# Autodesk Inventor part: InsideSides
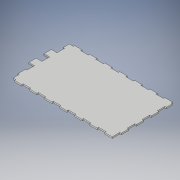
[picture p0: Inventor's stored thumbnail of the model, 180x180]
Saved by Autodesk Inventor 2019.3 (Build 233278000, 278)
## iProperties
Created: 2020-02
Part Number: InsideSides
Material: Generic
Document SubType Name: Modeling
Designer: KrystynWikoff
Density: 1 g/cm^3
Appearance: Default
Author: KrystynWikoff
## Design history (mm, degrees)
sketch "Sketch1"
  geometry: L1 (0, 0)-(174.142, 0); L2 (174.142, 0)-(174.142, -101.6); L3 (174.142, -101.6)-(0, -101.6); L4 (0, -101.6)-(0, 0)
  constraints: 8 end point, 2 parallel, 1 horizontal, 1 perpendicular
  dimensions: "d0" = 101.6 distance of L3.end L1.start; "d1" = 174.1424 distance of L1.start L1.end
extrude "Extrusion1" new body sketch "Sketch1" distance "d2" = 2.3622; taper "d3" = 0 deg
sketch "Sketch2" dims "d13" = 25.4
  geometry: L1 (-15.062, 0)-(-27.762, 0); L2 (-27.762, 0)-(-27.762, 2.362); L3 (-27.762, 2.362)-(-15.062, 2.362); L4 (-15.062, 2.362)-(-15.062, 0); L5 (0, 0)-(0, 101.6) reference; L6 (-174.142, 0)-(0, 0) reference; L7 (-40.462, 0)-(-53.162, 0); L8 (-53.162, 0)-(-53.162, 2.362); L9 (-53.162, 2.362)-(-40.462, 2.362); L10 (-40.462, 2.362)-(-40.462, 0); L11 (-65.862, 0)-(-78.562, 0); L12 (-78.562, 0)-(-78.562, 2.362); L13 (-78.562, 2.362)-(-65.862, 2.362); L14 (-65.862, 2.362)-(-65.862, 0); L15 (-91.262, 0)-(-103.962, 0); L16 (-103.962, 0)-(-103.962, 2.362); L17 (-103.962, 2.362)-(-91.262, 2.362); L18 (-91.262, 2.362)-(-91.262, 0); L19 (-116.662, 0)-(-129.362, 0); L20 (-129.362, 0)-(-129.362, 2.362); L21 (-129.362, 2.362)-(-116.662, 2.362); L22 (-116.662, 2.362)-(-116.662, 0); L23 (-142.062, 0)-(-154.762, 0); L24 (-154.762, 0)-(-154.762, 2.362); L25 (-154.762, 2.362)-(-142.062, 2.362); L26 (-142.062, 2.362)-(-142.062, 0); L27 (-167.462, 0)-(-180.162, 0); L28 (-180.162, 0)-(-180.162, 2.362); L29 (-180.162, 2.362)-(-167.462, 2.362); L30 (-167.462, 2.362)-(-167.462, 0)
  constraints: 56 end point, 2 horizontal, 2 parallel, 1 collinear, 1 perpendicular, 47 other
  dimensions: "d4" = 15.0622 distance between parallel lines of L5 L4; "d5" = 12.7 distance of L2.end L3.end; "d6" = 2.3622 distance of L3.end L1.start; "d7" = 0 distance between parallel lines of L6 L1; "d10" = 25.4 distance of L1.start L7.start
extrude "Extrusion2" cut sketch "Sketch2" distance "d15" = 2.3622; taper "d16" = 0 deg
sketch "Sketch3" dims "d25" = 25.4, "d35" = 25.4, "d44" = 25.4
  geometry: L1 (0, 0)-(0, 101.6) reference; L2 (0, 0)-(-2.362, 0); L3 (-2.362, 0)-(-2.362, 12.7); L4 (-2.362, 12.7)-(0, 12.7); L5 (0, 12.7)-(0, 0); L6 (-15.062, 0)-(0, 0) reference; L7 (0, 25.4)-(-2.362, 25.4); L8 (-2.362, 25.4)-(-2.362, 38.1); L9 (-2.362, 38.1)-(0, 38.1); L10 (0, 38.1)-(0, 25.4); L11 (0, 50.8)-(-2.362, 50.8); L12 (-2.362, 50.8)-(-2.362, 63.5); L13 (-2.362, 63.5)-(0, 63.5); L14 (0, 63.5)-(0, 50.8); L15 (0, 76.2)-(-2.362, 76.2); L16 (-2.362, 76.2)-(-2.362, 88.9); L17 (-2.362, 88.9)-(0, 88.9); L18 (0, 88.9)-(0, 76.2); L19 (-174.142, 101.6)-(-174.142, 2.362) reference; L20 (-174.142, 0)-(-171.78, 0); L21 (-171.78, 0)-(-171.78, 12.7); L22 (-171.78, 12.7)-(-174.142, 12.7); L23 (-174.142, 12.7)-(-174.142, 0); L24 (-167.462, 0)-(-154.762, 0) reference; L25 (-171.78, 38.1)-(-174.142, 38.1); L26 (-171.78, 25.4)-(-171.78, 38.1); L27 (-174.142, 38.1)-(-174.142, 25.4); L28 (-174.142, 25.4)-(-171.78, 25.4); L29 (-171.78, 63.5)-(-174.142, 63.5); L30 (-171.78, 50.8)-(-171.78, 63.5); L31 (-174.142, 63.5)-(-174.142, 50.8); L32 (-174.142, 50.8)-(-171.78, 50.8); L33 (-171.78, 88.9)-(-174.142, 88.9); L34 (-171.78, 76.2)-(-171.78, 88.9); L35 (-174.142, 88.9)-(-174.142, 76.2); L36 (-174.142, 76.2)-(-171.78, 76.2); L37 (-171.78, 114.3)-(-174.142, 114.3); L38 (-171.78, 101.6)-(-171.78, 114.3); L39 (-174.142, 114.3)-(-174.142, 101.6); L40 (-174.142, 101.6)-(-171.78, 101.6); L41 (0, 101.6)-(-2.362, 101.6); L42 (-2.362, 101.6)-(-2.362, 114.3); L43 (-2.362, 114.3)-(0, 114.3); L44 (0, 114.3)-(0, 101.6)
  constraints: 80 end point, 4 parallel, 3 vertical, 2 horizontal, 2 perpendicular, 2 point on line, 64 other
  dimensions: "d17" = 0 distance between parallel lines of L6 L2; "d18" = 12.7 distance of L2.end L3.end; "d19" = 2.3622 distance of L2.start L2.end; "d22" = 25.4 distance of L2.start L7.start; "d27" = 0 distance between parallel lines of L24 L20; "d28" = 2.3622 distance of L20.start L20.end; "d29" = 12.7 distance of L20.end L21.end; "d32" = 25.4 distance of L21.end L25.start; "d41" = 25.4 distance of L15.end L41.end
extrude "Extrusion3" cut sketch "Sketch3" distance "d37" = 2.3622; taper "d38" = 0 deg
sketch "Sketch4" dims "d56" = 25.4
  geometry: L1 (0, 101.6)-(-174.142, 101.6) reference; L2 (-27.762, 101.6)-(-15.062, 101.6); L3 (-15.062, 101.6)-(-15.062, 99.238); L4 (-15.062, 99.238)-(-27.762, 99.238); L5 (-27.762, 99.238)-(-27.762, 101.6); L6 (0, 88.9)-(0, 101.6) reference; L7 (0, 101.6)-(-2.362, 101.6); L8 (-2.362, 101.6)-(-2.362, 99.238); L9 (-2.362, 99.238)-(0, 99.238); L10 (0, 99.238)-(0, 101.6); L11 (-27.762, 101.6)-(-27.762, 99.238); L12 (-53.162, 101.6)-(-40.462, 101.6); L13 (-40.462, 101.6)-(-40.462, 99.238); L14 (-40.462, 99.238)-(-53.162, 99.238); L15 (-53.162, 99.238)-(-53.162, 101.6); L16 (-53.162, 101.6)-(-53.162, 99.238); L17 (-78.562, 101.6)-(-65.862, 101.6); L18 (-65.862, 101.6)-(-65.862, 99.238); L19 (-65.862, 99.238)-(-78.562, 99.238); L20 (-78.562, 99.238)-(-78.562, 101.6); L21 (-78.562, 101.6)-(-78.562, 99.238); L22 (-103.962, 101.6)-(-91.262, 101.6); L23 (-91.262, 101.6)-(-91.262, 99.238); L24 (-91.262, 99.238)-(-103.962, 99.238); L25 (-103.962, 99.238)-(-103.962, 101.6); L26 (-103.962, 101.6)-(-103.962, 99.238); L27 (-129.362, 101.6)-(-116.662, 101.6); L28 (-116.662, 101.6)-(-116.662, 99.238); L29 (-116.662, 99.238)-(-129.362, 99.238); L30 (-129.362, 99.238)-(-129.362, 101.6); L31 (-129.362, 101.6)-(-129.362, 99.238); L32 (-154.762, 101.6)-(-142.062, 101.6); L33 (-142.062, 101.6)-(-142.062, 99.238); L34 (-142.062, 99.238)-(-154.762, 99.238); L35 (-154.762, 99.238)-(-154.762, 101.6); L36 (-154.762, 101.6)-(-154.762, 99.238); L37 (-180.162, 101.6)-(-167.462, 101.6); L38 (-167.462, 101.6)-(-167.462, 99.238); L39 (-167.462, 99.238)-(-180.162, 99.238); L40 (-180.162, 99.238)-(-180.162, 101.6); 1 further point
  constraints: 76 end point, 4 parallel, 3 horizontal, 2 perpendicular, 1 point on line, 66 other
  dimensions: "d46" = 15.0622 distance between parallel lines of L6 L3; "d47" = 12.7 distance of L3.end L4.end; "d48" = 2.3622 distance of L4.end L2.start; "d49" = 2.3622 distance of L8.end L9.end; "d50" = 2.3622 distance of L7.end L8.end; "d53" = 25.4 distance of L7.end L11.start
extrude "Extrusion4" cut sketch "Sketch4" extent not by distance; stored distance "d58" = 0; taper "d59" = 0 deg
sketch "Sketch5"
  geometry: L1 (25.4, 0)-(12.7, 0) reference; L2 (0, 2.362)-(12.7, 2.362) reference; L3 (12.7, 0)-(0, 0); L4 (0, 0)-(0, 2.362); L5 (0, 2.362)-(12.7, 2.362); L6 (12.7, 2.362)-(12.7, 0); L7 (-12.7, 0)-(-25.4, 0) reference; L8 (-25.4, 2.362)-(-12.7, 2.362) reference; L9 (-12.7, 0)-(-25.4, 0); L10 (-25.4, 0)-(-25.4, 2.362); L11 (-25.4, 2.362)-(-12.7, 2.362); L12 (-12.7, 2.362)-(-12.7, 0); 1 further point
  constraints: 16 end point, 4 parallel, 2 horizontal, 2 perpendicular
extrude "Extrusion5" join sketch "Sketch5" distance "d60" = 7.1628; taper "d61" = 0 deg
body "Solid1"
